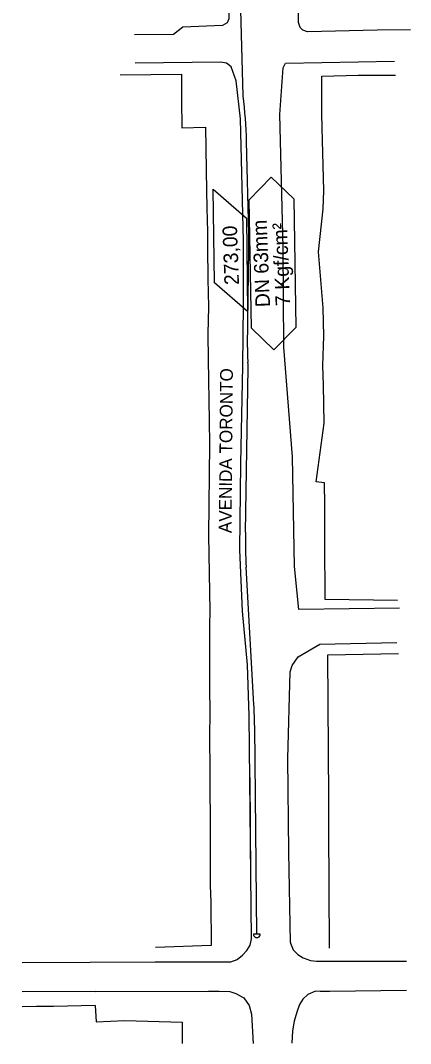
# Model space of a CAD drawing. Extents: x 325899 to 364828, y 7568995 to 7592502.
# Drawn here: x 359639 to 359921, y 7568995 to 7569735 of the extents above; entities that cross this region are included whole.
import ezdxf

# ---------------------------------------------------------------- set-up
doc = ezdxf.new("R2010")
doc.units = 0
for name, color, linetype in [('MEIO-FIO', 7, 'Continuous'), ('MURO_DIVISA', 7, 'Continuous'), ('SIMBOLO', 7, 'Continuous'), ('TEXTO', 7, 'Continuous'), ('TUBO_PEAD_GN_63', 7, 'Continuous')]:
    doc.layers.add(name, color=color, linetype=linetype)

msp = doc.modelspace()

# ---------------------------------------------------------------- linework, layer by layer
at = {"layer": 'MEIO-FIO'}
for p, q in [((359805.9, 7569116.96), (359805.35, 7569187.48)), ((359905.26, 7569054.67), (359918.29, 7569054.7)), ((359905.26, 7569054.67), (359918.29, 7569054.7)), ((359693.47, 7569032.64), (359640.75, 7569032.46))]:
    msp.add_line(p, q, dxfattribs=at)
for points in [[(359921.19, 7569727.68), (359897.16, 7569727.48), (359846.69, 7569726.47), (359843.39, 7569727.62), (359841.38, 7569729.59), (359840.15, 7569733.06), (359839.52, 7569787.19), (359839.3, 7569840.97), (359838.86, 7569908.96), (359838.69, 7570007.19), (359840.39, 7570011.61), (359852.39, 7570021.74), (359866, 7570028.71), (359876.08, 7570032.36), (359889.19, 7570032), (359903.24, 7570026.23), (359907.84, 7570020.17), (359911.19, 7570010.1)], [(359921.19, 7569727.68), (359897.16, 7569727.48), (359846.69, 7569726.47), (359843.39, 7569727.62), (359841.38, 7569729.59), (359840.15, 7569733.06), (359839.52, 7569787.19), (359839.3, 7569840.97), (359838.86, 7569908.96), (359838.69, 7570007.19), (359840.39, 7570011.61), (359852.39, 7570021.74), (359866, 7570028.71), (359876.08, 7570032.36), (359889.19, 7570032), (359903.24, 7570026.23), (359907.84, 7570020.17), (359911.19, 7570010.1)], [(359639.44, 7569970.85), (359684.55, 7569970.71), (359771.1, 7569972.45), (359772.88, 7569972.18), (359775.18, 7569971.7), (359777.88, 7569970.71), (359780.84, 7569969.24), (359783.38, 7569967.62), (359786.82, 7569964.19), (359788.85, 7569957.96), (359789.3, 7569848.75), (359789.62, 7569775.75), (359789.87, 7569735.69), (359788.79, 7569732.74), (359785.34, 7569730.92), (359756.83, 7569729.83), (359749.89, 7569724.53), (359721.87, 7569724.12)], [(359806.37, 7569070.85), (359804.68, 7569231.91), (359803.47, 7569268.73), (359799.75, 7569307.58), (359797.91, 7569351.94), (359798.61, 7569414.39), (359799.97, 7569485.04), (359800.56, 7569529.12), (359800.59, 7569575.15), (359798.48, 7569663.44), (359795.26, 7569690.89), (359791.56, 7569701.11), (359788.33, 7569703.63), (359783.88, 7569704.5), (359722.31, 7569703.82)], [(359913.28, 7569309.66), (359840.53, 7569308.89), (359837.35, 7569339.82), (359836.01, 7569419.1), (359829.57, 7569498.54), (359829.22, 7569570.45), (359826.89, 7569666.57), (359829.23, 7569700.28), (359830.87, 7569703.82), (359909.59, 7569705.21)], [(359834.48, 7569068.07), (359833.4, 7569133.66), (359832.62, 7569200.98), (359834.26, 7569263.82), (359835.64, 7569268.41), (359840.14, 7569274.5), (359855.65, 7569283.67), (359911.34, 7569284.93)], [(359736.69, 7569054.01), (359783.62, 7569054.07), (359791.39, 7569054.21), (359795.95, 7569055.87), (359799.91, 7569058.83), (359802.92, 7569062.24), (359805.26, 7569066.23), (359806.21, 7569070.67), (359805.9, 7569116.96)], [(359834.48, 7569068.07), (359834.48, 7569068.07), (359834.48, 7569068.07), (359834.37, 7569067.65), (359836.51, 7569062.78), (359839.68, 7569059.42), (359843.58, 7569057.08), (359848.86, 7569055.13), (359853.36, 7569054.56), (359905.29, 7569054.67)], [(359640.72, 7569053.64), (359689.75, 7569053.95), (359737.64, 7569054.01)], [(359693.47, 7569032.64), (359775.37, 7569033), (359783, 7569032.97), (359790.71, 7569032.59), (359794.91, 7569031.21), (359800.73, 7569027.99), (359804.66, 7569022.62), (359806.37, 7569016.28), (359807.48, 7568995.17)], [(359918.32, 7569033.34), (359862.88, 7569032.6), (359855.96, 7569032.63), (359852.51, 7569032.88), (359847.04, 7569030.49), (359843.42, 7569027.11), (359841.05, 7569023.31), (359838.95, 7569017.85), (359837.11, 7569011.12), (359835.97, 7569004.26), (359835.49, 7568995.24)]]:
    msp.add_lwpolyline(points, dxfattribs=at)
at = {"layer": 'MURO_DIVISA'}
msp.add_line((359777.26, 7569065.92), (359736.99, 7569064.54), dxfattribs=at)
for points in [[(359711.44, 7569695.32), (359755.85, 7569695.68), (359755.78, 7569676.98), (359755.99, 7569656.95), (359772.99, 7569657.42), (359773.85, 7569611.54), (359774, 7569599.16), (359774.47, 7569581.74), (359774.63, 7569570.22), (359774.76, 7569547.8), (359775.2, 7569527.46), (359774.89, 7569508.02), (359774.92, 7569489.61), (359775.75, 7569445.07), (359775.93, 7569428.25), (359775.25, 7569362.61), (359776.23, 7569307.54), (359775.92, 7569297.38), (359775.99, 7569283.8), (359775.94, 7569264.05), (359775.97, 7569254.72), (359776.2, 7569231.48), (359775.96, 7569220), (359776.22, 7569189.54), (359776.35, 7569146.37), (359776.34, 7569109.29), (359776.85, 7569097.17), (359777.26, 7569065.92)], [(359911.84, 7569315.42), (359859.57, 7569315.91), (359859.3, 7569357.91), (359859.21, 7569384.21), (359859.12, 7569400.41), (359853.04, 7569401.09), (359858.82, 7569443.57), (359858.39, 7569471.07), (359857.81, 7569485.27), (359858.53, 7569506.31), (359858.09, 7569526.86), (359854.71, 7569567.27), (359858.18, 7569598.53), (359858.49, 7569611.52), (359858.11, 7569629.87), (359857.51, 7569647.86), (359857.05, 7569666.89), (359857.04, 7569694.37), (359883.44, 7569695.01), (359910.29, 7569694.97)], [(359862.65, 7569063.92), (359862.15, 7569151.34), (359862.16, 7569172.2), (359861.38, 7569276.03), (359912.58, 7569276.92)], [(359693.49, 7569022.44), (359663.34, 7569021.76), (359651.02, 7569021.84), (359640.77, 7569021.62)], [(359693.49, 7569022.44), (359694.09, 7569010.85), (359714.76, 7569011.72), (359756.23, 7569010.53), (359756.26, 7568995.06)]]:
    msp.add_lwpolyline(points, dxfattribs=at)
at = {"layer": 'SIMBOLO'}
msp.add_lwpolyline([(359822.54, 7569496.43), (359806.21, 7569512.25), (359804.75, 7569605.02), (359820.58, 7569621.35), (359836.9, 7569605.53), (359838.36, 7569512.75), (359822.54, 7569496.43)], dxfattribs=at)
msp.add_lwpolyline([(359802.59, 7569591.76), (359803.48, 7569524.28), (359779.5, 7569545.04), (359778.61, 7569612.52)], close=True, dxfattribs=at)
at = {"layer": 'TUBO_PEAD_GN_63'}
for p, q in [((359800.36, 7569680.18), (359792.7, 7569957.75)), ((359804.31, 7569580.58), (359802.72, 7569647.14)), ((359803.35, 7569498.19), (359804.4, 7569569.78)), ((359801.96, 7569364.58), (359803.79, 7569483.51)), ((359803.78, 7569486.98), (359803.73, 7569487.61)), ((359808.08, 7569240.05), (359802.47, 7569339.48)), ((359810.19, 7569074.03), (359808.61, 7569224.02)), ((359812.63, 7569074.03), (359807.75, 7569074.04))]:
    msp.add_line(p, q, dxfattribs=at)
for centre, radius, start, end in [((359452.82, 7569638.77), 350, 1.37061, 6.79621), ((359454.41, 7569572.21), 350, 359.60254, 1.37061), ((359908.34, 7569496.65), 105, 179.15707, 184.93923), ((359793.32, 7569486.07), 10.5, 359.52058, 4.93923), ((359453.84, 7569488.91), 350, 359.11602, 359.52058), ((360151.92, 7569359.18), 350, 179.11602, 183.22737), ((359458.63, 7569220.35), 350, 0.60236, 3.22737), ((359810.19, 7569074.03), 2.44, 179.85908, 359.85908)]:
    msp.add_arc(centre, radius, start, end, dxfattribs=at)

# ---------------------------------------------------------------- texts
at = {"layer": 'TEXTO'}
for s, height, rotation, p in [('DN 63mm', 10.5, 92.29067, (359819.77, 7569527.54)), ('7 Kgf/cm²', 10.5, 92.29067, (359834.28, 7569528.44)), ('273,00', 10.5, 92.0817, (359797.33, 7569543.55)), ('AVENIDA TORONTO', 9.2211, 89.50983, (359791.88, 7569363.97))]:
    msp.add_text(s, height=height, rotation=rotation, dxfattribs=at).set_placement(p)

doc.saveas('drawing.dxf')
